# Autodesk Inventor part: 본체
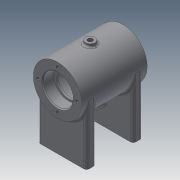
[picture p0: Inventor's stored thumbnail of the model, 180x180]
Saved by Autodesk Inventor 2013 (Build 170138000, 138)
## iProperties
Created: 2020-07
Part Number: 본체
Material: Generic
Document SubType Name: Modeling
Designer: user
Density: 1 g/cm^3
Author: user
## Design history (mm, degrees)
sketch "스케치1"
  geometry: C1 r 26 at (0, 0); 1 further point
  constraints: 1 centre point, 1 coincident
  dimensions: "d0" = 52 diameter of C1
extrude "돌출1" new body sketch "스케치1" stored distance "d2" = 70; taper "d3" = 0 deg
node "작업 평면1"
sketch "스케치2"
  geometry: L1 (-26, 0)-(26, 0); L2 (26, 0)-(26, -64); L3 (26, -64)-(-26, -64); L4 (-26, -64)-(-26, 0); C1 r 26 at (0, 0) reference; 2 further points
  constraints: 8 end point, 2 parallel, 1 coincident, 1 horizontal, 1 midpoint, 1 perpendicular
  dimensions: "d5" = 52 distance of L1.start L1.end; "d7" = 64 distance of L1.end L2.end
extrude "돌출2" join sketch "스케치2" distance "d8" = 10; taper "d9" = 0 deg
sketch "스케치7"
  geometry: L1 (0, 0)-(9.919, -27.251); L2 (9.919, -27.251)-(15.557, -25.199); L3 (15.557, -25.199)-(6.385, 0); L4 (0, 0)-(6.385, 0); L5 (6.385, 0)-(5.638, 2.052); L6 (5.638, 2.052)-(0, 0); L7 (0, 0)-(0, -26); 2 further points
  constraints: 14 end point, 3 perpendicular, 1 collinear, 1 horizontal alignment, 1 parallel, 1 vertical alignment, 1 other
  dimensions: "d44" = 6 distance of L1.end L2.end; "d74" = 29 distance between parallel lines of L2 L6; "d75" = 20 deg angle of L1 L7
revolve "회전2" sketch "스케치7" stored, may be unused: angle "d47" = 90 deg
sketch "스케치3"
  geometry: L1 (26, -35)-(-26, -35) reference; L2 (-26, -35)-(-26, -30) reference; L3 (-26, -30)-(-64, -30) reference; L4 (-64, -30)-(-64, -20) reference; L5 (-64, -20)-(-26, -20) reference; L6 (-26, -20)-(-26, 20) reference; L7 (-26, 20)-(-64, 20) reference; L8 (-64, 20)-(-64, 30) reference; L9 (-64, 30)-(-26, 30) reference; L10 (-26, 30)-(-26, 35) reference; L11 (-26, 35)-(26, 35) reference; L12 (26, 35)-(26, -35) reference; L13 (0, 35)-(0, -35); L14 (0, 35)-(16, 35); L15 (16, 35)-(16, 23); L16 (16, 23)-(14, 23); L17 (14, 23)-(14, 21); L18 (14, 21)-(21, 21); L19 (21, 21)-(21, -21); L20 (21, -21)-(14, -21); L21 (14, -21)-(14, -23); L22 (14, -23)-(16, -23); L23 (16, -23)-(16, -35); L24 (16, -35)-(0, -35); 1 further point
  constraints: 24 end point, 6 parallel, 2 collinear, 2 midpoint, 2 perpendicular, 2 point on line
  dimensions: "d10" = 12 distance of L14.end L15.end; "d12" = 42 distance of L18.end L19.end; "d13" = 12 distance of L22.end L23.end; "d14" = 2 distance of L16.end L17.end; "d16" = 32 diameter of L15 L13; "d17" = 28 diameter of L17 L13; "d18" = 42 diameter of L19 L13; "d19" = 28 diameter of L21 L13; "d20" = 32 diameter of L23 L13
revolve "회전1" sketch "스케치3" stored, may be unused: angle "d15" = 90 deg
sketch "스케치4" dims "d21" = 42
  geometry: C1 r 26 at (0, 0) reference; 2 further points
  constraints: 2 vertical alignment, 1 coincident, 2 other
hole "구멍1" sketch "스케치4" at (0, 21) diameter "d22" = 3.242; stored, may be unused: countersink angle "d26" = 90 deg, drill point angle "d28" = 118 deg; dims "d23" = 8, "d24" = 4, "d25" = 2, "d27" = 10
node "작업 평면2"
sketch "스케치5"
  geometry: C1 r 5 at (0, 0); 1 further point
  constraints: 1 centre point, 1 coincident
  dimensions: "d33" = 10 diameter of C1
extrude "돌출3" join sketch "스케치5" stored distance "d34" = 10; taper "d35" = 0 deg
sketch "스케치6"
  geometry: C1 r 5 at (0, 0) reference; 1 further point
  constraints: 1 coincident
hole "구멍2" sketch "스케치6" at (0, 0) diameter "d36" = 5.188; stored, may be unused: countersink angle "d40" = 90 deg, drill point angle "d42" = 118 deg; dims "d37" = 8, "d38" = 4, "d39" = 2, "d41" = 10
sketch "스케치8"
  geometry: C1 r 6 at (0, 0) reference; 1 further point
  constraints: 1 coincident
hole "구멍3" sketch "스케치8" at (0, 0) diameter "d48" = 5.188; stored, may be unused: countersink angle "d52" = 90 deg, drill point angle "d54" = 118 deg; dims "d49" = 8, "d50" = 4, "d51" = 2, "d53" = 20
sketch "스케치9"
  geometry: L1 (0, 10)-(52, 10) reference; 3 further points
  constraints: 1 horizontal alignment
  dimensions: "d55" = 40 distance of point (6, 5) point (46, 5); "d57" = 5 distance from line of point (6, 5) L1; "d58" = 20 horizontal distance of point (46, 5) point (26, -20)
hole "구멍4" sketch "스케치9" at (46, 5), (6, 5) diameter "d59" = 4.134; stored, may be unused: countersink angle "d63" = 90 deg, drill point angle "d65" = 118 deg; dims "d60" = 8, "d61" = 4, "d62" = 2, "d64" = 10
fillet "모깎기1" dims "d66" = 3
fillet "모깎기2" dims "d67" = 0.3
fillet "모깎기4" dims "d69" = 3
chamfer "모따기1" distance "d70" = 1; stored, may be unused: second distance "d71" = 2, angle "d72" = 45 deg
fillet "모깎기5" dims "d73" = 3
fillet "모깎기6" dims "d76" = 2
fillet "모깎기7" dims "d77" = 2
node "작업 평면3"
sketch "스케치10"
  geometry: L1 (-26, -35)-(-26, 35) reference; L2 (-26, -35)-(26, -35) reference; 2 further points
  constraints: 1 other
  dimensions: "d79" = 26 distance from line of point (0, 0) L1; "d80" = 35 distance from line of point (0, 0) L2
feature "엠보싱1" sketch "스케치10" dims "d10" = 12, "d12" = 42, "d13" = 12, "d14" = 2, "d16" = 32, "d17" = 28, "d18" = 42, "d19" = 28, "d20" = 32, "d81" = 0.5, "d82" = 0
node "솔리드1"
mirror "대칭1"
pattern_circular "원형 패턴1" dims angle "d30" = 360 deg
mirror "대칭2"
mirror "대칭3"
node "절단 모서리 투영1"
node "절단 모서리 투영2"
node "절단 모서리 투영3"
other parameters: "d32" = 29, "d78" = -75
